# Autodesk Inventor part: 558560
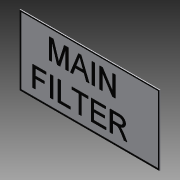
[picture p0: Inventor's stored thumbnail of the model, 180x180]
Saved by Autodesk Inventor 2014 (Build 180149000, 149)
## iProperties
Shininess: 20.0
Length Units: 11272
Angle Units: 11279
Time Units: 11290
Mass Units: 11286
Length Display Precision: 3
Angle Display Precision: 2
Company: Autodesk, Inc.
Created: 2002-08
Part Number: 558560
Material: Generic
Description: DECAL;A; HYD FILTER
Document SubType Name: Modeling
Designer: Autodesk, Inc.
Density: 1 g/cm^3
Mass: 0.865186 g
Surface Area: 61.0954 cm^2
Volume: 0.865186 cm^3
Appearance: White (Flat)
Density: 0.0
Volumn: 0.0
Area: 0.0
PropertySet Name: Model Information
Control State: 0
Master: False
Checked Out: False
Last Check In By: JT
Last Check In Date: 2003-06-20
Title: DECAL;A; HYD FILTER
Author: Autodesk, Inc.
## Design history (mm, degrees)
sketch "Sketch1"
  geometry: L1 (0, 0)-(76.2, 0); L2 (76.2, 0)-(76.2, 38.1); L3 (76.2, 38.1)-(0, 38.1); L4 (0, 38.1)-(0, 0)
  constraints: 8 end point, 2 parallel, 1 horizontal, 1 perpendicular
  dimensions: "d3" = 76.2 distance of L1.start L1.end; "d4" = 38.1 distance of L3.end L1.start
extrude "Extrusion2" new body sketch "Sketch1" distance "d5" = 0.254; taper "d6" = 0 deg
sketch "Sketch2"
  geometry: L1 (0, 0)-(0, 38.1) reference; L2 (76.2, 0)-(0, 0) reference; L3 (76.2, 38.1)-(76.2, 0) reference; L4 (0, 38.1)-(76.2, 38.1) reference; L5 (15.967, 22.187)-(15.967, 33.299); L6 (15.967, 33.299)-(18.232, 33.299); L7 (18.232, 33.299)-(20.703, 25.463); L8 (21.743, 25.599)-(24.173, 33.299); L9 (24.173, 33.299)-(26.436, 33.299); L10 (26.436, 33.299)-(26.436, 22.187); L11 (26.436, 22.187)-(24.986, 22.187); L12 (24.986, 22.187)-(24.986, 31.689); L13 (24.986, 31.689)-(22.022, 22.187); L14 (22.022, 22.187)-(20.379, 22.187); L15 (20.379, 22.187)-(17.417, 31.689); L16 (17.417, 31.689)-(17.417, 22.187); L17 (17.417, 22.187)-(15.967, 22.187); L18 (27.478, 22.187)-(31.919, 33.299); L19 (31.919, 33.299)-(33.353, 33.299); L20 (33.353, 33.299)-(37.795, 22.187); L21 (37.795, 22.187)-(36.26, 22.187); L22 (36.26, 22.187)-(35.014, 25.569); L23 (35.014, 25.569)-(30.258, 25.569); L24 (30.258, 25.569)-(29.013, 22.187); L25 (29.013, 22.187)-(27.478, 22.187); L26 (30.734, 26.857)-(34.539, 26.857); L27 (34.539, 26.857)-(33.436, 29.837); L28 (31.891, 29.998)-(30.734, 26.857); L29 (39.32, 22.187)-(39.32, 33.299); L30 (39.32, 33.299)-(40.769, 33.299); L31 (40.769, 33.299)-(40.769, 22.187); L32 (40.769, 22.187)-(39.32, 22.187); L33 (43.507, 22.187)-(43.507, 33.299); L34 (43.507, 33.299)-(45.05, 33.299); L35 (45.05, 33.299)-(50.593, 24.698); L36 (50.593, 24.698)-(50.593, 33.299); L37 (50.593, 33.299)-(52.043, 33.299); L38 (52.043, 33.299)-(52.043, 22.187); L39 (52.043, 22.187)-(50.5, 22.187); L40 (50.5, 22.187)-(44.957, 30.788); L41 (44.957, 30.788)-(44.957, 22.187); L42 (44.957, 22.187)-(43.507, 22.187); L43 (6.963, 4.684)-(6.963, 15.797); L44 (6.963, 15.797)-(14.372, 15.797); L45 (14.372, 15.797)-(14.372, 14.508); L46 (14.372, 14.508)-(8.413, 14.508); L47 (8.413, 14.508)-(8.413, 10.965); L48 (8.413, 10.965)-(13.405, 10.965); L49 (13.405, 10.965)-(13.405, 9.677); L50 (13.405, 9.677)-(8.413, 9.677); L51 (8.413, 9.677)-(8.413, 4.684); L52 (8.413, 4.684)-(6.963, 4.684); L53 (16.626, 4.684)-(16.626, 15.797); L54 (16.626, 15.797)-(18.076, 15.797); L55 (18.076, 15.797)-(18.076, 4.684); L56 (18.076, 4.684)-(16.626, 4.684); L57 (20.814, 4.684)-(20.814, 15.797); L58 (20.814, 15.797)-(22.263, 15.797); L59 (22.263, 15.797)-(22.263, 5.973); L60 (22.263, 5.973)-(27.578, 5.973); L61 (27.578, 5.973)-(27.578, 4.684); L62 (27.578, 4.684)-(20.814, 4.684); L63 (32.087, 4.684)-(32.087, 14.508); L64 (32.087, 14.508)-(28.383, 14.508)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; 27 further points
  constraints: 186 end point, 47 other
extrude "Extrusion3" join sketch "Sketch2" distance "d7" = 0.254; taper "d8" = 0 deg
body "Solid1"
